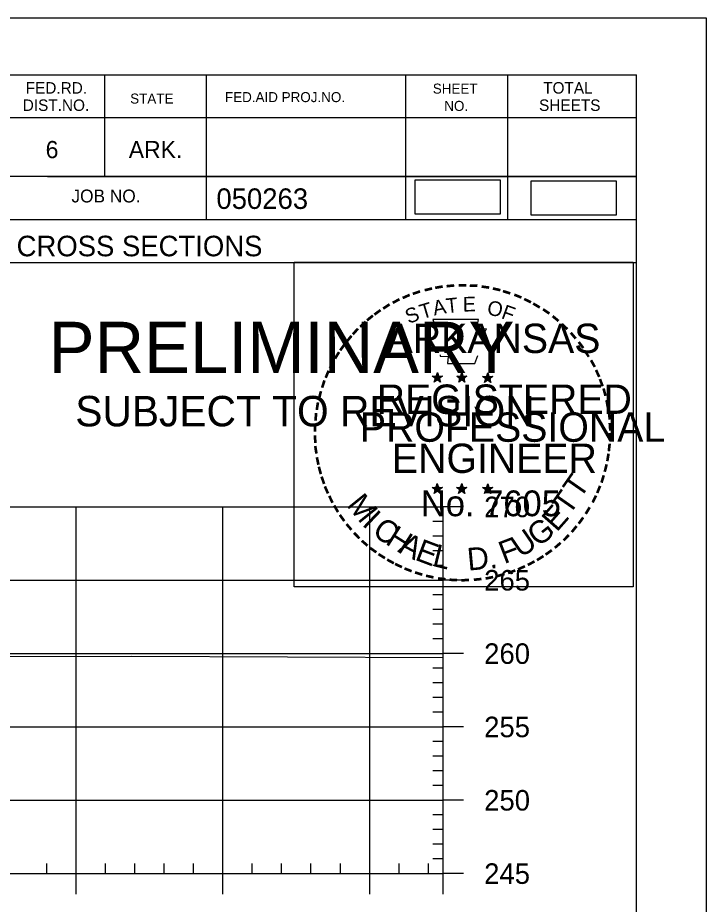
# Model space of a CAD drawing. Extents: x 1365647 to 1367999, y 387113 to 400173.
# Drawn here: x 1366010.1 to 1366057, y 389445.7 to 389506.1 of the extents above; entities that cross this region are included whole.
import ezdxf

# ---------------------------------------------------------------- set-up
doc = ezdxf.new("R2010")
doc.units = 0
for name, color, linetype in [('R_Axis', 7, 'Continuous'), ('R_Axis Annot', 7, 'Continuous'), ('R_Border', 7, 'Continuous'), ('R_Border PE', 7, 'Continuous'), ('R_Border Prem', 7, 'Continuous'), ('R_Detour', 7, 'Continuous'), ('R_Exist Surface', 7, 'Continuous'), ('R_Grid', 7, 'Continuous'), ('R_No Plot', 7, 'Continuous')]:
    doc.layers.add(name, color=color, linetype=linetype)

msp = doc.modelspace()

# ---------------------------------------------------------------- linework, layer by layer
at = {"layer": 'R_Axis'}
for p, q in [((1366039.095, 389447.759), (1366039.095, 389472.759)), ((1366040.495, 389472.759), (1366039.095, 389472.759)), ((1366039.095, 389471.759), (1366038.395, 389471.759)), ((1366039.095, 389470.759), (1366038.395, 389470.759)), ((1366039.095, 389469.759), (1366038.395, 389469.759)), ((1366039.095, 389468.759), (1366038.395, 389468.759)), ((1366040.495, 389467.759), (1366039.095, 389467.759)), ((1366039.095, 389466.759), (1366038.395, 389466.759)), ((1366039.095, 389465.759), (1366038.395, 389465.759)), ((1366039.095, 389464.759), (1366038.395, 389464.759)), ((1366039.095, 389463.759), (1366038.395, 389463.759)), ((1366040.495, 389462.759), (1366039.095, 389462.759)), ((1366039.095, 389461.759), (1366038.395, 389461.759)), ((1366039.095, 389460.759), (1366038.395, 389460.759)), ((1366039.095, 389459.759), (1366038.395, 389459.759)), ((1366039.095, 389458.759), (1366038.395, 389458.759)), ((1366040.495, 389457.759), (1366039.095, 389457.759)), ((1366039.095, 389456.759), (1366038.395, 389456.759)), ((1366039.095, 389455.759), (1366038.395, 389455.759)), ((1366039.095, 389454.759), (1366038.395, 389454.759)), ((1366039.095, 389453.759), (1366038.395, 389453.759)), ((1366040.495, 389452.759), (1366039.095, 389452.759)), ((1366039.095, 389451.759), (1366038.395, 389451.759)), ((1366039.095, 389450.759), (1366038.395, 389450.759)), ((1366039.095, 389449.759), (1366038.395, 389449.759)), ((1366012.095, 389447.759), (1366012.095, 389448.459)), ((1366016.095, 389447.759), (1366016.095, 389448.459)), ((1366018.095, 389447.759), (1366018.095, 389448.459)), ((1366020.095, 389447.759), (1366020.095, 389448.459)), ((1366022.095, 389447.759), (1366022.095, 389448.459)), ((1366026.095, 389447.759), (1366026.095, 389448.459)), ((1366028.095, 389447.759), (1366028.095, 389448.459)), ((1366030.095, 389447.759), (1366030.095, 389448.459)), ((1366032.095, 389447.759), (1366032.095, 389448.459)), ((1366036.095, 389447.759), (1366036.095, 389448.459)), ((1366038.095, 389447.759), (1366038.095, 389448.459)), ((1366039.095, 389448.759), (1366038.395, 389448.759)), ((1365749.095, 389447.759), (1366039.095, 389447.759)), ((1366014.095, 389446.359), (1366014.095, 389447.759)), ((1366024.095, 389446.359), (1366024.095, 389447.759)), ((1366034.095, 389446.359), (1366034.095, 389447.759)), ((1366039.095, 389446.359), (1366039.095, 389447.759)), ((1366040.495, 389447.759), (1366039.095, 389447.759))]:
    msp.add_line(p, q, dxfattribs=at)
at = {"layer": 'R_Border'}
for p, q in [((1365736.095, 389502.219), (1366052.275, 389502.219)), ((1366016.015, 389502.219), (1366016.015, 389495.279)), ((1366022.955, 389502.219), (1366022.955, 389492.339)), ((1366036.535, 389502.219), (1366036.535, 389492.339)), ((1366043.475, 389502.219), (1366043.475, 389492.339)), ((1366052.275, 389296.759), (1366052.275, 389502.219)), ((1366052.275, 389499.279), (1366009.175, 389499.279)), ((1366052.275, 389499.299), (1366052.275, 389499.299)), ((1366052.275, 389495.279), (1366009.175, 389495.279)), ((1366012.135, 389495.279), (1366052.275, 389495.279)), ((1366052.275, 389492.339), (1365970.015, 389492.339)), ((1366009.175, 389489.419), (1366052.275, 389489.419))]:
    msp.add_line(p, q, dxfattribs=at)
at = {"layer": 'R_Border PE'}
for p, q in [((1366038.356, 389481.665), (1366038.705, 389481.554)), ((1366038.356, 389481.665), (1366038.609, 389481.62)), ((1366038.356, 389481.665), (1366038.593, 389481.543)), ((1366038.489, 389481.257), (1366038.705, 389481.554)), ((1366038.489, 389481.257), (1366038.615, 389481.501)), ((1366038.489, 389481.257), (1366038.703, 389481.474)), ((1366038.705, 389481.919), (1366038.664, 389481.667)), ((1366038.918, 389481.257), (1366038.703, 389481.471)), ((1366038.705, 389481.554), (1366038.705, 389481.919)), ((1366038.705, 389481.919), (1366038.754, 389481.669)), ((1366039.052, 389481.665), (1366038.705, 389481.554)), ((1366038.918, 389481.257), (1366038.705, 389481.554)), ((1366039.052, 389481.665), (1366038.766, 389481.616)), ((1366038.918, 389481.257), (1366038.781, 389481.548)), ((1366039.052, 389481.665), (1366038.848, 389481.563)), ((1366040.026, 389481.665), (1366040.375, 389481.554)), ((1366040.026, 389481.665), (1366040.279, 389481.62)), ((1366040.026, 389481.665), (1366040.263, 389481.543)), ((1366040.159, 389481.257), (1366040.375, 389481.554)), ((1366040.159, 389481.257), (1366040.285, 389481.501)), ((1366040.159, 389481.257), (1366040.373, 389481.474)), ((1366040.375, 389481.919), (1366040.334, 389481.667)), ((1366040.588, 389481.257), (1366040.373, 389481.471)), ((1366040.375, 389481.554), (1366040.375, 389481.919)), ((1366040.375, 389481.919), (1366040.424, 389481.669)), ((1366040.722, 389481.665), (1366040.375, 389481.554)), ((1366040.588, 389481.257), (1366040.375, 389481.554)), ((1366040.722, 389481.665), (1366040.436, 389481.616)), ((1366040.588, 389481.257), (1366040.451, 389481.548)), ((1366040.722, 389481.665), (1366040.518, 389481.563)), ((1366041.79, 389481.653), (1366042.139, 389481.542)), ((1366041.79, 389481.653), (1366042.043, 389481.608)), ((1366041.79, 389481.653), (1366042.027, 389481.531)), ((1366041.923, 389481.245), (1366042.139, 389481.542)), ((1366041.923, 389481.245), (1366042.049, 389481.489)), ((1366041.923, 389481.245), (1366042.137, 389481.462)), ((1366042.139, 389481.907), (1366042.098, 389481.655)), ((1366042.352, 389481.245), (1366042.137, 389481.459)), ((1366042.139, 389481.542), (1366042.139, 389481.907)), ((1366042.139, 389481.907), (1366042.188, 389481.657)), ((1366042.486, 389481.653), (1366042.139, 389481.542)), ((1366042.352, 389481.245), (1366042.139, 389481.542)), ((1366042.486, 389481.653), (1366042.2, 389481.604)), ((1366042.352, 389481.245), (1366042.215, 389481.536)), ((1366042.486, 389481.653), (1366042.282, 389481.551)), ((1366038.701, 389474.346), (1366038.66, 389474.094)), ((1366038.701, 389473.981), (1366038.701, 389474.346)), ((1366038.701, 389474.346), (1366038.75, 389474.096)), ((1366040.37, 389474.346), (1366040.329, 389474.094)), ((1366040.37, 389473.981), (1366040.37, 389474.346)), ((1366040.37, 389474.346), (1366040.419, 389474.096)), ((1366042.137, 389474.336), (1366042.096, 389474.084)), ((1366042.137, 389473.971), (1366042.137, 389474.336)), ((1366042.137, 389474.336), (1366042.186, 389474.086)), ((1366038.352, 389474.092), (1366038.701, 389473.981)), ((1366038.352, 389474.092), (1366038.605, 389474.047)), ((1366038.352, 389474.092), (1366038.589, 389473.97)), ((1366038.485, 389473.684), (1366038.701, 389473.981)), ((1366038.485, 389473.684), (1366038.611, 389473.928)), ((1366038.485, 389473.684), (1366038.699, 389473.901)), ((1366038.914, 389473.684), (1366038.699, 389473.898)), ((1366039.048, 389474.092), (1366038.701, 389473.981)), ((1366038.914, 389473.684), (1366038.701, 389473.981)), ((1366039.048, 389474.092), (1366038.762, 389474.043)), ((1366038.914, 389473.684), (1366038.777, 389473.975)), ((1366039.048, 389474.092), (1366038.844, 389473.99)), ((1366040.021, 389474.092), (1366040.37, 389473.981)), ((1366040.021, 389474.092), (1366040.274, 389474.047)), ((1366040.021, 389474.092), (1366040.258, 389473.97)), ((1366040.154, 389473.684), (1366040.37, 389473.981)), ((1366040.154, 389473.684), (1366040.28, 389473.928)), ((1366040.154, 389473.684), (1366040.368, 389473.901)), ((1366040.583, 389473.684), (1366040.368, 389473.898)), ((1366040.717, 389474.092), (1366040.37, 389473.981)), ((1366040.583, 389473.684), (1366040.37, 389473.981)), ((1366040.717, 389474.092), (1366040.431, 389474.043)), ((1366040.583, 389473.684), (1366040.446, 389473.975)), ((1366040.717, 389474.092), (1366040.513, 389473.99)), ((1366041.788, 389474.082), (1366042.137, 389473.971)), ((1366041.788, 389474.082), (1366042.041, 389474.037)), ((1366041.788, 389474.082), (1366042.025, 389473.96)), ((1366041.921, 389473.674), (1366042.137, 389473.971)), ((1366041.921, 389473.674), (1366042.047, 389473.918)), ((1366041.921, 389473.674), (1366042.135, 389473.891)), ((1366042.35, 389473.674), (1366042.135, 389473.888)), ((1366042.484, 389474.082), (1366042.137, 389473.971)), ((1366042.35, 389473.674), (1366042.137, 389473.971)), ((1366042.484, 389474.082), (1366042.198, 389474.033)), ((1366042.35, 389473.674), (1366042.213, 389473.965)), ((1366042.484, 389474.082), (1366042.28, 389473.98))]:
    msp.add_line(p, q, dxfattribs=at)
for points in [[(1366038.397, 389485.543), (1366038.666, 389484.716)], [(1366041.908, 389484.621), (1366042.05, 389484.905), (1366041.365, 389484.881), (1366041.513, 389485.543), (1366038.397, 389485.543)], [(1366038.889, 389483.12), (1366038.889, 389483.033), (1366039.452, 389483.014), (1366039.398, 389482.541), (1366041.268, 389482.541), (1366041.469, 389483.077)], [(1366038.705, 389481.919), (1366038.918, 389481.257), (1366038.356, 389481.665), (1366039.052, 389481.665), (1366038.489, 389481.257), (1366038.705, 389481.919)], [(1366040.375, 389481.919), (1366040.588, 389481.257), (1366040.026, 389481.665), (1366040.722, 389481.665), (1366040.159, 389481.257), (1366040.375, 389481.919)], [(1366042.139, 389481.907), (1366042.352, 389481.245), (1366041.79, 389481.653), (1366042.486, 389481.653), (1366041.923, 389481.245), (1366042.139, 389481.907)], [(1366038.701, 389474.346), (1366038.914, 389473.684), (1366038.352, 389474.092), (1366039.048, 389474.092), (1366038.485, 389473.684), (1366038.701, 389474.346)], [(1366040.37, 389474.346), (1366040.583, 389473.684), (1366040.021, 389474.092), (1366040.717, 389474.092), (1366040.154, 389473.684), (1366040.37, 389474.346)], [(1366042.137, 389474.336), (1366042.35, 389473.674), (1366041.788, 389474.082), (1366042.484, 389474.082), (1366041.921, 389473.674), (1366042.137, 389474.336)]]:
    msp.add_lwpolyline(points, dxfattribs=at)
for centre, radius in [((1366038.704, 389481.554), 0.172), ((1366038.704, 389481.554), 0.145), ((1366038.704, 389481.554), 0.116), ((1366038.704, 389481.554), 0.0991), ((1366038.704, 389481.554), 0.0747), ((1366038.704, 389481.554), 0.0495), ((1366038.704, 389481.554), 0.0296), ((1366040.374, 389481.554), 0.172), ((1366040.374, 389481.554), 0.145), ((1366040.374, 389481.554), 0.116), ((1366040.374, 389481.554), 0.0991), ((1366040.374, 389481.554), 0.0747), ((1366040.374, 389481.554), 0.0495), ((1366040.374, 389481.554), 0.0296), ((1366042.138, 389481.542), 0.172), ((1366042.138, 389481.542), 0.145), ((1366042.138, 389481.542), 0.116), ((1366042.138, 389481.542), 0.0991), ((1366042.138, 389481.542), 0.0747), ((1366042.138, 389481.542), 0.0495), ((1366042.138, 389481.542), 0.0296), ((1366038.7, 389473.981), 0.172), ((1366038.7, 389473.981), 0.145), ((1366038.7, 389473.981), 0.116), ((1366038.7, 389473.981), 0.0991), ((1366038.7, 389473.981), 0.0747), ((1366038.7, 389473.981), 0.0495), ((1366038.7, 389473.981), 0.0296), ((1366040.369, 389473.981), 0.172), ((1366040.369, 389473.981), 0.145), ((1366040.369, 389473.981), 0.116), ((1366040.369, 389473.981), 0.0991), ((1366040.369, 389473.981), 0.0747), ((1366040.369, 389473.981), 0.0495), ((1366040.369, 389473.981), 0.0296), ((1366042.136, 389473.971), 0.172), ((1366042.136, 389473.971), 0.145), ((1366042.136, 389473.971), 0.116), ((1366042.136, 389473.971), 0.0991), ((1366042.136, 389473.971), 0.0747), ((1366042.136, 389473.971), 0.0495), ((1366042.136, 389473.971), 0.0296)]:
    msp.add_circle(centre, radius, dxfattribs=at)
at = {"layer": 'R_Detour'}
for points in [[(1366037.165, 389492.738), (1366042.998, 389492.738), (1366042.998, 389495.049), (1366037.165, 389495.049)], [(1366045.079, 389492.664), (1366050.912, 389492.664), (1366050.912, 389494.975), (1366045.079, 389494.975)]]:
    msp.add_lwpolyline(points, close=True, dxfattribs=at)
at = {"layer": 'R_Exist Surface'}
msp.add_lwpolyline([(1365956.506, 389462.813), (1365969.446, 389462.559), (1365991.752, 389462.528), (1365994.704, 389462.53), (1365996.996, 389462.537), (1366017.884, 389462.591), (1366039.095, 389462.496)], dxfattribs=at)
at = {"layer": 'R_Grid'}
for p, q in [((1365749.095, 389472.759), (1366039.095, 389472.759)), ((1366014.095, 389447.759), (1366014.095, 389472.759)), ((1366024.095, 389447.759), (1366024.095, 389472.759)), ((1366034.095, 389447.759), (1366034.095, 389472.759)), ((1366039.095, 389447.759), (1366039.095, 389472.759)), ((1365749.095, 389467.759), (1366039.095, 389467.759)), ((1365749.095, 389462.759), (1366039.095, 389462.759)), ((1365749.095, 389457.759), (1366039.095, 389457.759)), ((1365749.095, 389452.759), (1366039.095, 389452.759)), ((1365749.095, 389447.759), (1366039.095, 389447.759))]:
    msp.add_line(p, q, dxfattribs=at)
at = {"layer": 'R_No Plot'}
msp.add_line((1365723.694, 389506.113), (1366057.027, 389506.113), dxfattribs=at)
for points in [[(1365723.687, 389506.113), (1366057.027, 389506.113), (1366057.027, 389292.776), (1365723.687, 389292.776)], [(1366028.946, 389489.451), (1366052.044, 389489.451), (1366052.044, 389467.301), (1366028.946, 389467.301)]]:
    msp.add_lwpolyline(points, close=True, dxfattribs=at)

# ---------------------------------------------------------------- texts
at = {"layer": 'R_Axis Annot'}
for s, p in [('270', (1366041.895, 389472.059)), ('265', (1366041.895, 389467.059)), ('260', (1366041.895, 389462.059)), ('255', (1366041.895, 389457.059)), ('250', (1366041.895, 389452.059)), ('245', (1366041.895, 389447.059))]:
    msp.add_text(s, height=1.4, dxfattribs=at).set_placement(p)
at = {"layer": 'R_Border'}
for s, height, p in [('FED.RD.', 0.7819, (1366010.655, 389500.939)), ('SHEET', 0.684, (1366038.395, 389500.939)), ('TOTAL', 0.7819, (1366045.915, 389500.939)), ('STATE', 0.684, (1366017.775, 389500.259)), ('FED.AID PROJ.NO.', 0.684, (1366024.235, 389500.359)), ('DIST.NO.', 0.7819, (1366010.455, 389499.759)), ('NO.', 0.684, (1366039.175, 389499.759)), ('SHEETS', 0.7819, (1366045.635, 389499.759)), ('6', 1.172, (1366012.015, 389496.539)), ('ARK.', 1.1723, (1366017.675, 389496.539)), ('JOB NO.', 0.8792, (1366013.775, 389493.519)), ('050263', 1.4, (1366023.651, 389493.078)), ('CROSS SECTIONS', 1.4, (1366010.038, 389489.849))]:
    msp.add_text(s, height=height, rotation=360, dxfattribs=at).set_placement(p)
at = {"layer": 'R_Border PE'}
for s, height, rotation, p in [('-', 1.6, 19.17608, (1366037.145, 389486.67)), ('-', 1.6, 13.63015, (1366037.895, 389486.911)), ('-', 1.6, 10.21935, (1366038.573, 389487.073)), ('-', 1.6, 5.89682, (1366039.302, 389487.183)), ('-', 1.6, 0.18623, (1366040.074, 389487.255)), ('-', 1.6, 357.74304, (1366040.797, 389487.242)), ('-', 1.6, 352.16172, (1366041.541, 389487.186)), ('-', 1.6, 347.20489, (1366042.26, 389487.072)), ('-', 1.6, 342.3362, (1366042.895, 389486.917)), ('-', 1.6, 28.79182, (1366035.878, 389486.084)), ('-', 1.6, 24.30721, (1366036.511, 389486.401)), ('A', 1, 11.21318, (1366038.492, 389485.803)), ('T', 1, 6.02276, (1366039.341, 389485.969)), ('E', 1, 0.83234, (1366040.446, 389486.079)), ('-', 1.6, 337.85509, (1366043.63, 389486.694)), ('-', 1.6, 334.12109, (1366044.261, 389486.423)), ('-', 1.6, 34.06357, (1366035.281, 389485.714)), ('S', 1, 21.59401, (1366036.752, 389485.221)), ('T', 1, 16.4036, (1366037.666, 389485.552)), ('O', 1, 350.4515, (1366042.05, 389485.869)), ('F', 1, 340.07066, (1366043.004, 389485.641)), ('-', 1.6, 329.64089, (1366044.84, 389486.14)), ('-', 1.6, 325.86266, (1366045.483, 389485.779)), ('-', 1.6, 38.95066, (1366034.227, 389484.941)), ('-', 1.6, 36.23174, (1366034.703, 389485.319)), ('-', 1.6, 320.52971, (1366046.093, 389485.353)), ('-', 1.6, 42.96224, (1366033.794, 389484.524)), ('ARKANSAS', 2, 360, (1366035.25, 389483.255)), ('-', 1.6, 315.57859, (1366046.692, 389484.865)), ('-', 1.6, 50.61417, (1366032.943, 389483.56)), ('-', 1.6, 48.42305, (1366033.346, 389484.046)), ('-', 1.6, 309.87973, (1366047.261, 389484.315)), ('-', 1.6, 54.23247, (1366032.53, 389482.993)), ('-', 1.6, 306.65218, (1366047.786, 389483.713)), ('-', 1.6, 58.07063, (1366032.205, 389482.466)), ('-', 1.4, 303.67529, (1366048.272, 389483.145)), ('-', 1.6, 62.87135, (1366031.892, 389481.852)), ('-', 1.6, 299.66835, (1366048.591, 389482.538)), ('-', 1.6, 67.77427, (1366031.633, 389481.241)), ('-', 1.6, 294.66279, (1366048.915, 389481.926)), ('DWB', 0.01, 360, (1366038.691, 389481.549)), ('DWB', 0.01, 360, (1366040.361, 389481.549)), ('DWB', 0.01, 360, (1366042.125, 389481.537)), ('-', 1.6, 290.57283, (1366049.172, 389481.349)), ('-', 1.6, 72.39447, (1366031.414, 389480.611)), ('REGISTERED', 2, 360, (1366034.572, 389479.106)), ('-', 1.6, 285.12326, (1366049.406, 389480.769)), ('-', 1.6, 75.46096, (1366031.217, 389479.897)), ('-', 1.6, 81.20126, (1366031.085, 389479.184)), ('-', 1.6, 280.54934, (1366049.606, 389480.027)), ('-', 1.6, 85.18634, (1366031.009, 389478.493)), ('PROFESSIONAL', 2, 360, (1366033.424, 389477.202)), ('-', 1.6, 276.59616, (1366049.768, 389479.259)), ('-', 1.6, 89.06224, (1366030.984, 389477.792)), ('-', 1.6, 274.33011, (1366049.828, 389478.537)), ('-', 1.6, 94.19588, (1366031.019, 389477.067)), ('-', 1.6, 269.94067, (1366049.862, 389477.905)), ('-', 1.6, 98.94793, (1366031.091, 389476.4)), ('ENGINEER', 2, 360, (1366035.611, 389475.077)), ('-', 1.6, 263.5172, (1366049.843, 389477.239)), ('-', 1.6, 101.71495, (1366031.226, 389475.667)), ('-', 1.6, 260.99529, (1366049.772, 389476.585)), ('-', 1.6, 105.45785, (1366031.388, 389475.072)), ('-', 1.6, 255.7626, (1366049.662, 389475.907)), ('-', 1.6, 109.08742, (1366031.603, 389474.441)), ('T', 1.54, 55.05496, (1366048.42, 389473.246)), ('-', 1.6, 252.86809, (1366049.481, 389475.187)), ('-', 1.6, 114.06432, (1366031.857, 389473.845)), ('-', 1.6, 247.88866, (1366049.258, 389474.514)), ('M', 1.54, 308.91747, (1366032.472, 389472.872)), ('No. 7605', 1.757, 360, (1366037.585, 389472.126)), ('DWB', 0.01, 360, (1366038.686, 389473.977)), ('DWB', 0.01, 360, (1366040.355, 389473.975)), ('DWB', 0.01, 360, (1366042.122, 389473.966)), ('T', 1.54, 55.05496, (1366047.689, 389472.126)), ('-', 1.6, 115.72885, (1366032.162, 389473.227)), ('-', 1.6, 244.61971, (1366048.996, 389473.885)), ('-', 1.6, 120.44712, (1366032.519, 389472.641)), ('I', 1.54, 316.46364, (1366033.514, 389471.552)), ('E', 1.54, 48.73133, (1366046.843, 389470.999)), ('-', 1.6, 239.07125, (1366048.602, 389473.133)), ('-', 1.6, 125.89344, (1366032.922, 389472.08)), ('C', 1.54, 324.01974, (1366034.187, 389470.929)), ('G', 1.54, 38.21734, (1366045.59, 389469.979)), ('-', 1.6, 233.84524, (1366048.2, 389472.48)), ('-', 1.6, 130.71812, (1366033.384, 389471.528)), ('H', 1.54, 327.53419, (1366035.097, 389470.274)), ('U', 1.54, 34.40523, (1366044.391, 389469.246)), ('-', 1.6, 231.25377, (1366047.77, 389471.914)), ('-', 1.6, 134.22381, (1366033.901, 389470.983)), ('A', 1.54, 332.55127, (1366035.951, 389469.737)), ('F', 1.54, 20.82016, (1366043.254, 389468.852)), ('-', 1.6, 225.76533, (1366047.291, 389471.35)), ('-', 1.6, 138.93382, (1366034.426, 389470.519)), ('-', 1.6, 144.64634, (1366034.982, 389470.113)), ('E', 1.54, 339.20679, (1366037.109, 389469.175)), ('L', 1.54, 346.2929, (1366038.301, 389468.751)), ('D.', 1.54, 5.26016, (1366040.804, 389468.414)), ('-', 1.6, 221.08509, (1366046.769, 389470.841)), ('-', 1.6, 148.08978, (1366035.543, 389469.742)), ('-', 1.6, 212.24909, (1366045.686, 389469.982)), ('-', 1.6, 215.73633, (1366046.22, 389470.369)), ('-', 1.6, 151.57039, (1366036.122, 389469.417)), ('-', 1.6, 154.60019, (1366036.644, 389469.17)), ('-', 1.6, 204.25161, (1366044.504, 389469.317)), ('-', 1.6, 207.35684, (1366045.128, 389469.636)), ('-', 1.6, 158.56121, (1366037.268, 389468.916)), ('-', 1.6, 162.79826, (1366037.955, 389468.703)), ('-', 1.6, 167.55551, (1366038.67, 389468.539)), ('-', 1.6, 195.47429, (1366043.208, 389468.802)), ('-', 1.6, 200.71842, (1366043.885, 389469.044)), ('-', 1.6, 173.11546, (1366039.442, 389468.429)), ('-', 1.6, 176.51827, (1366040.19, 389468.376)), ('-', 1.6, 181.59176, (1366040.934, 389468.395)), ('-', 1.6, 185.81666, (1366041.743, 389468.471)), ('-', 1.6, 191.28576, (1366042.479, 389468.603))]:
    msp.add_text(s, height=height, rotation=rotation, dxfattribs=at).set_placement(p)
at = {"layer": 'R_Border Prem'}
for s, height, p in [('PRELIMINARY', 3.5, (1366012.226, 389481.882)), ('DWB', 0.01, (1366012.973, 389483.731)), ('SUBJECT TO REVISION', 2.07511, (1366014.035, 389478.253))]:
    msp.add_text(s, height=height, rotation=360, dxfattribs=at).set_placement(p)

doc.saveas('drawing.dxf')
